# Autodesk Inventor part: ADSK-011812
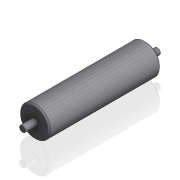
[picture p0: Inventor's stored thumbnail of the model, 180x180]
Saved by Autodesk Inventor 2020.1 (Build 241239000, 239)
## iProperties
Created: 2000-02
Part Number: ADSK-011812
Material: Pearson HRS
Document SubType Name: Modeling
Designer: cmcgourin
Density: 7.83 g/cm^3
Appearance: Métal - Acier
Mass: 5535.18 g
Surface Area: 640.795 cm^2
Volume: 706.92 cm^3
Control State: 0
Checked Out: False
Master: False
Shininess: 0.0
Length Units: 11269
Angle Units: 11279
Time Units: 11290
Mass Units: 11283
Length Display Precision: 3
Angle Display Precision: 2
Compacted: True
Cutlength: 23.25
Material Desc: Material Description goes here
Material_Number: Pearson
Dimensions: 63,5x282x63,5 mm
Mass: 5,535 kg
VLT_Material: Pearson HRS
Density: 0.0
Volumn: 0.0
Area: 0.0
PropertySet Name: Model Information
Author: cmcgourin
Revision Number: -
Title: ADSK-011812
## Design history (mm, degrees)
node "Extrusion1" dims "d1" = 232, "d2" = 0
  sketch "Sketch1"
    geometry: C1 r 6.747 at (0, 6.35) reference; C2 r 31.75 at (0, 6.35); 1 further point
    constraints: 1 centre point, 1 coincident
    dimensions: "d0" = 63.5 diameter of C2
node "Extrusion2" dims "d3" = 25, "d4" = 0
  sketch "Sketch2"
    geometry: C1 r 6.747 at (0, 0) reference
node "Chamfer1" dims "d7" = 3, "d8" = 3, "d11" = 45 deg
node "Chamfer2" dims "d9" = 1, "d10" = 1, "d12" = 45 deg
mirror "Spiegeln1"
node "Solide1"
node "Corps solides"
node "Corps surfaciques"
